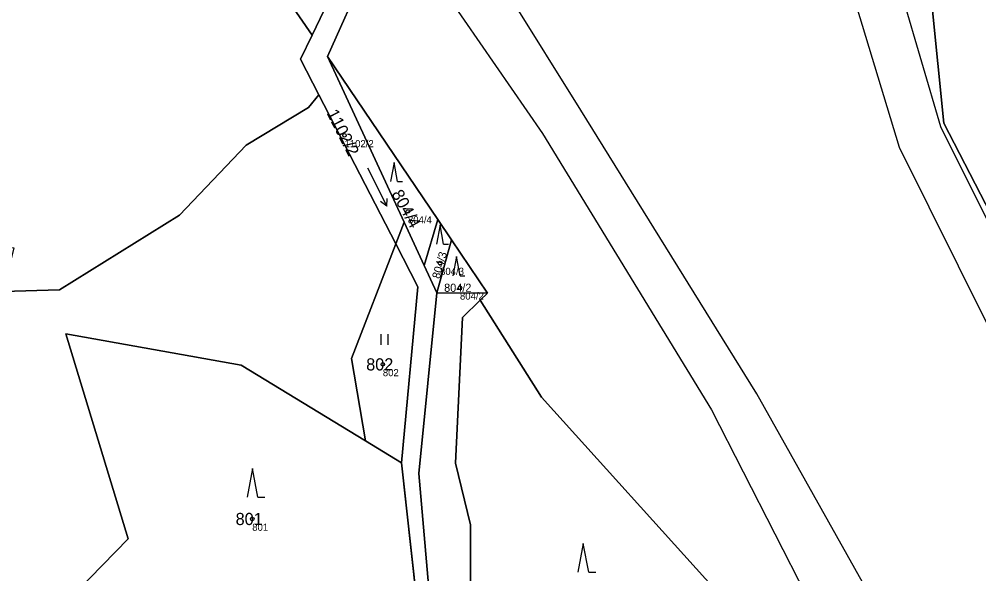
# Model space of a CAD drawing. Extents: x -554500 to -548272, y -1079733 to -1073730.
# Drawn here: x -551733.2 to -551598.9, y -1076398.9 to -1076321.4 of the extents above; entities that cross this region are included whole.
import ezdxf

# ---------------------------------------------------------------- set-up
doc = ezdxf.new("R2010")
doc.units = 0
for name, color, linetype in [('Definiční body', 7, 'Continuous'), ('Hranice parcel', 7, 'Continuous'), ('Parcelní čísla', 7, 'Continuous'), ('Polygon parcely', 7, 'Continuous'), ('Vnitřní kresba', 7, 'Continuous'), ('Značky kultur', 7, 'Continuous')]:
    doc.layers.add(name, color=color, linetype=linetype)

msp = doc.modelspace()

# ---------------------------------------------------------------- linework, layer by layer
at = {"layer": 'Definiční body'}
for centre in [(-551687.68, -1076337.61994), (-551678.81, -1076348.25994), (-551674.31, -1076355.46994), (-551671.53, -1076358.91994), (-551682.32, -1076369.62994), (-551700.59, -1076391.23994)]:
    msp.add_circle(centre, 0.25, dxfattribs=at)
at = {"layer": 'Hranice parcel'}
for p, q in [((-551684.89, -1076308.33), (-551692.21, -1076323.59)), ((-551684.81, -1076314.8), (-551690.07, -1076326.58)), ((-551690.07, -1076326.58), (-551679.34, -1076349.74)), ((-551690.07, -1076326.58), (-551674.63, -1076349.39)), ((-551680.51, -1076352.78), (-551691.26, -1076331.97)), ((-551674.63, -1076349.39), (-551676.52, -1076355.83)), ((-551674.63, -1076349.39), (-551672.72, -1076352.22)), ((-551679.34, -1076349.74), (-551680.51, -1076352.78)), ((-551679.34, -1076349.74), (-551676.52, -1076355.83)), ((-551672.72, -1076352.22), (-551674.77, -1076359.61)), ((-551672.72, -1076352.22), (-551667.67, -1076359.68)), ((-551676.52, -1076355.83), (-551674.77, -1076359.61)), ((-551667.67, -1076359.68), (-551674.77, -1076359.61)), ((-551667.67, -1076359.68), (-551668.68, -1076360.64)), ((-551679.7, -1076383.39), (-551684.76, -1076380.31)), ((-551677.32, -1076404.87), (-551679.7, -1076383.39))]:
    msp.add_line(p, q, dxfattribs=at)
for points in [[(-551664.29, -1076203.7), (-551689.85, -1076204.91), (-551726.2, -1076243.62), (-551728.52, -1076271.01), (-551692.21, -1076323.59)], [(-551612.88, -1076245.99), (-551603.81, -1076335.92), (-551589.23, -1076364.16), (-551551.65, -1076413.34), (-551482.17, -1076491.9), (-551416.37, -1076563.88), (-551403.4, -1076574.29), (-551394.57, -1076580.04), (-551382.37, -1076584.61), (-551375.33, -1076584.51), (-551367.79, -1076582.03), (-551359, -1076576.12), (-551355.92, -1076570.24), (-551353.25, -1076560.02), (-551356.43, -1076547.11), (-551366.06, -1076533.16), (-551431.52, -1076493.43), (-551453.64, -1076487.39), (-551474.61, -1076473.65), (-551491.3, -1076449.66), (-551517.82, -1076362.05), (-551514.11, -1076329.03), (-551510.06, -1076315.85)], [(-551692.21, -1076323.59), (-551693.84, -1076326.98), (-551691.26, -1076331.97)], [(-551691.26, -1076331.97), (-551692.72, -1076333.72), (-551701.42, -1076338.97), (-551710.78, -1076348.77), (-551727.54, -1076359.19), (-551735.43, -1076359.46)], [(-551684.76, -1076380.31), (-551686.68, -1076368.81), (-551680.51, -1076352.78)], [(-551679.7, -1076383.39), (-551677.41, -1076358.77), (-551680.51, -1076352.78)], [(-551674.77, -1076359.61), (-551677.28, -1076384.89), (-551675.46, -1076405.8), (-551682.1, -1076418.3), (-551704.93, -1076417.48), (-551718.41, -1076419.65), (-551725.74, -1076426.42), (-551736.15, -1076430.17), (-551758.98, -1076419.56), (-551781.2, -1076419.08), (-551798.91, -1076429.59)], [(-551668.68, -1076360.64), (-551671.18, -1076363.1), (-551672.15, -1076383.45), (-551670.03, -1076392.04), (-551669.99, -1076414.69)], [(-551635.47, -1076401.53), (-551660.12, -1076374.21), (-551668.68, -1076360.64)], [(-551677.32, -1076404.87), (-551704.51, -1076409.49), (-551705.76, -1076405.33), (-551722.4, -1076406.55), (-551725.11, -1076401.4), (-551717.96, -1076394.01), (-551726.68, -1076365.38), (-551702.13, -1076369.76), (-551684.76, -1076380.31)]]:
    msp.add_lwpolyline(points, dxfattribs=at)
at = {"layer": 'Polygon parcely'}
for points in [[(-551728.52, -1076271.01), (-551692.21, -1076323.59), (-551684.89, -1076308.33), (-551684.3, -1076303.95), (-551684.06, -1076302.5), (-551683.24, -1076297.51), (-551698.68, -1076270.27), (-551694.7, -1076261.2), (-551676.97, -1076220.75), (-551673.06, -1076211.84), (-551670.59, -1076209.6), (-551664.29, -1076203.7), (-551689.85, -1076204.91), (-551726.2, -1076243.62)], [(-551684.81, -1076314.8), (-551684.89, -1076308.33), (-551692.21, -1076323.59), (-551693.84, -1076326.98), (-551691.26, -1076331.97), (-551680.51, -1076352.78), (-551679.34, -1076349.74), (-551690.07, -1076326.58)], [(-551679.34, -1076349.74), (-551676.52, -1076355.83), (-551674.63, -1076349.39), (-551690.07, -1076326.58)], [(-551676.52, -1076355.83), (-551674.77, -1076359.61), (-551672.72, -1076352.22), (-551674.63, -1076349.39)], [(-551680.51, -1076352.78), (-551686.68, -1076368.81), (-551684.76, -1076380.31), (-551679.7, -1076383.39), (-551677.41, -1076358.77)], [(-551672.72, -1076352.22), (-551674.77, -1076359.61), (-551667.67, -1076359.68)], [(-551651.61, -1076421.66), (-551646.97, -1076431.33), (-551642.4, -1076440.87), (-551631.43, -1076437.02), (-551628.49, -1076435.99), (-551635.47, -1076401.53), (-551660.12, -1076374.21), (-551668.68, -1076360.64), (-551671.18, -1076363.1), (-551672.15, -1076383.45), (-551670.03, -1076392.04), (-551669.99, -1076414.69), (-551682.94, -1076452.8), (-551678.77, -1076452.38)], [(-551677.32, -1076404.87), (-551679.7, -1076383.39), (-551684.76, -1076380.31), (-551702.13, -1076369.76), (-551726.68, -1076365.38), (-551717.96, -1076394.01), (-551725.11, -1076401.4), (-551722.4, -1076406.55), (-551705.76, -1076405.33), (-551704.51, -1076409.49)]]:
    msp.add_lwpolyline(points, close=True, dxfattribs=at)
for points in [[(-551355.92, -1076570.24), (-551359, -1076576.12), (-551367.79, -1076582.03), (-551375.33, -1076584.51), (-551382.37, -1076584.61), (-551394.57, -1076580.04), (-551403.4, -1076574.29), (-551416.37, -1076563.88), (-551482.17, -1076491.9), (-551551.65, -1076413.34), (-551589.23, -1076364.16), (-551603.81, -1076335.92), (-551612.88, -1076245.99)], [(-551612.88, -1076245.99), (-551603.81, -1076335.92), (-551589.23, -1076364.16), (-551551.65, -1076413.34), (-551482.17, -1076491.9), (-551416.37, -1076563.88), (-551403.4, -1076574.29), (-551394.57, -1076580.04), (-551382.37, -1076584.61), (-551375.33, -1076584.51), (-551367.79, -1076582.03), (-551359, -1076576.12), (-551355.92, -1076570.24), (-551353.25, -1076560.02), (-551356.43, -1076547.11), (-551366.06, -1076533.16), (-551431.52, -1076493.43), (-551453.64, -1076487.39), (-551474.61, -1076473.65), (-551491.3, -1076449.66), (-551517.82, -1076362.05), (-551514.11, -1076329.03), (-551510.06, -1076315.85)], [(-551816.28, -1076313.27), (-551800.16, -1076324.48), (-551762.02, -1076334.8), (-551756.68, -1076350.2), (-551733.93, -1076353.36), (-551735.43, -1076359.46), (-551727.54, -1076359.19), (-551710.78, -1076348.77), (-551701.42, -1076338.97), (-551692.72, -1076333.72), (-551691.26, -1076331.97), (-551693.84, -1076326.98), (-551692.21, -1076323.59), (-551728.52, -1076271.01)], [(-551684.81, -1076314.8), (-551690.07, -1076326.58), (-551674.63, -1076349.39), (-551672.72, -1076352.22), (-551667.67, -1076359.68), (-551668.68, -1076360.64), (-551660.12, -1076374.21), (-551635.47, -1076401.53)], [(-551736.69, -1076399.13), (-551726.73, -1076424.16), (-551719.33, -1076417.64), (-551703.55, -1076415.01), (-551683.43, -1076416.1), (-551677.32, -1076404.87), (-551704.51, -1076409.49), (-551705.76, -1076405.33), (-551722.4, -1076406.55), (-551725.11, -1076401.4), (-551717.96, -1076394.01), (-551726.68, -1076365.38), (-551702.13, -1076369.76), (-551684.76, -1076380.31), (-551686.68, -1076368.81), (-551680.51, -1076352.78), (-551691.26, -1076331.97), (-551692.72, -1076333.72), (-551701.42, -1076338.97), (-551710.78, -1076348.77), (-551727.54, -1076359.19), (-551735.43, -1076359.46)], [(-551736.15, -1076430.17), (-551725.74, -1076426.42), (-551718.41, -1076419.65), (-551704.93, -1076417.48), (-551682.1, -1076418.3), (-551675.46, -1076405.8), (-551677.28, -1076384.89), (-551674.77, -1076359.61), (-551676.52, -1076355.83), (-551679.34, -1076349.74), (-551680.51, -1076352.78), (-551677.41, -1076358.77), (-551679.7, -1076383.39), (-551677.32, -1076404.87), (-551683.43, -1076416.1), (-551703.55, -1076415.01), (-551719.33, -1076417.64), (-551726.73, -1076424.16), (-551736.41, -1076427.56)], [(-551669.99, -1076414.69), (-551670.03, -1076392.04), (-551672.15, -1076383.45), (-551671.18, -1076363.1), (-551668.68, -1076360.64), (-551667.67, -1076359.68), (-551674.77, -1076359.61), (-551677.28, -1076384.89), (-551675.46, -1076405.8)]]:
    msp.add_lwpolyline(points, dxfattribs=at)
at = {"layer": 'Vnitřní kresba'}
for p, q in [((-551654.6, -1076334.11), (-551677.24, -1076297.86)), ((-551681.18, -1076306.67), (-551659.98, -1076337.36)), ((-551604.24, -1076336.42), (-551609.9, -1076317.12)), ((-551610.02, -1076339.31), (-551616.02, -1076319.67)), ((-551629.99, -1076373.75), (-551654.6, -1076334.11)), ((-551659.98, -1076337.36), (-551636.34, -1076376)), ((-551590.58, -1076363.92), (-551604.24, -1076336.42)), ((-551597.64, -1076364.23), (-551610.02, -1076339.31)), ((-551610.43, -1076408.56), (-551629.99, -1076373.75)), ((-551636.34, -1076376), (-551617.08, -1076413.57))]:
    msp.add_line(p, q, dxfattribs=at)
at = {"layer": 'Značky kultur'}
for p, q in [((-551680.75, -1076341.41), (-551681.252, -1076344.09)), ((-551680.248, -1076344.09), (-551680.75, -1076341.41)), ((-551684.462, -1076342.176), (-551681.738, -1076347.522)), ((-551680.248, -1076344.09), (-551679.58, -1076344.09)), ((-551681.738, -1076347.522), (-551681.735, -1076346.424)), ((-551681.738, -1076347.522), (-551682.628, -1076346.879)), ((-551674.32, -1076350.13), (-551674.822, -1076352.81)), ((-551673.818, -1076352.81), (-551674.32, -1076350.13)), ((-551673.818, -1076352.81), (-551673.15, -1076352.81)), ((-551672, -1076354.57), (-551672.502, -1076357.25)), ((-551671.498, -1076357.25), (-551672, -1076354.57)), ((-551671.498, -1076357.25), (-551670.83, -1076357.25)), ((-551682.571, -1076366.9), (-551682.571, -1076365.4)), ((-551681.57, -1076366.9), (-551681.57, -1076365.4)), ((-551700.57, -1076384.18), (-551701.32, -1076388.18)), ((-551699.82, -1076388.18), (-551700.57, -1076384.18)), ((-551699.82, -1076388.18), (-551698.824, -1076388.18)), ((-551654.27, -1076394.68), (-551655.02, -1076398.68)), ((-551653.52, -1076398.68), (-551654.27, -1076394.68)), ((-551653.52, -1076398.68), (-551652.524, -1076398.68))]:
    msp.add_line(p, q, dxfattribs=at)

# ---------------------------------------------------------------- texts
at = {"layer": 'Definiční body'}
for s, p in [('1102/2', (-551687.68, -1076339.276)), ('804/4', (-551678.81, -1076349.916)), ('804/3', (-551674.31, -1076357.126)), ('804/2', (-551671.53, -1076360.576)), ('802', (-551682.32, -1076371.286)), ('801', (-551700.59, -1076392.896))]:
    msp.add_text(s, height=0.999996, dxfattribs=at).set_placement(p)
at = {"layer": 'Parcelní čísla'}
for s, height, rotation, p in [('1102/2', 1.699998, 297, (-551690.229, -1076334.488)), ('804/4', 1.699998, 298.9999972, (-551681.152, -1076345.787)), ('804/3', 1.14, 74, (-551674.371, -1076357.753))]:
    msp.add_text(s, height=height, rotation=rotation, dxfattribs=at).set_placement(p)
for s, height, p in [('804/2', 1.14, (-551673.741, -1076359.49)), ('802', 1.699998, (-551684.645, -1076370.48)), ('801', 1.699998, (-551702.915, -1076392.09))]:
    msp.add_text(s, height=height, dxfattribs=at).set_placement(p)

doc.saveas('drawing.dxf')
